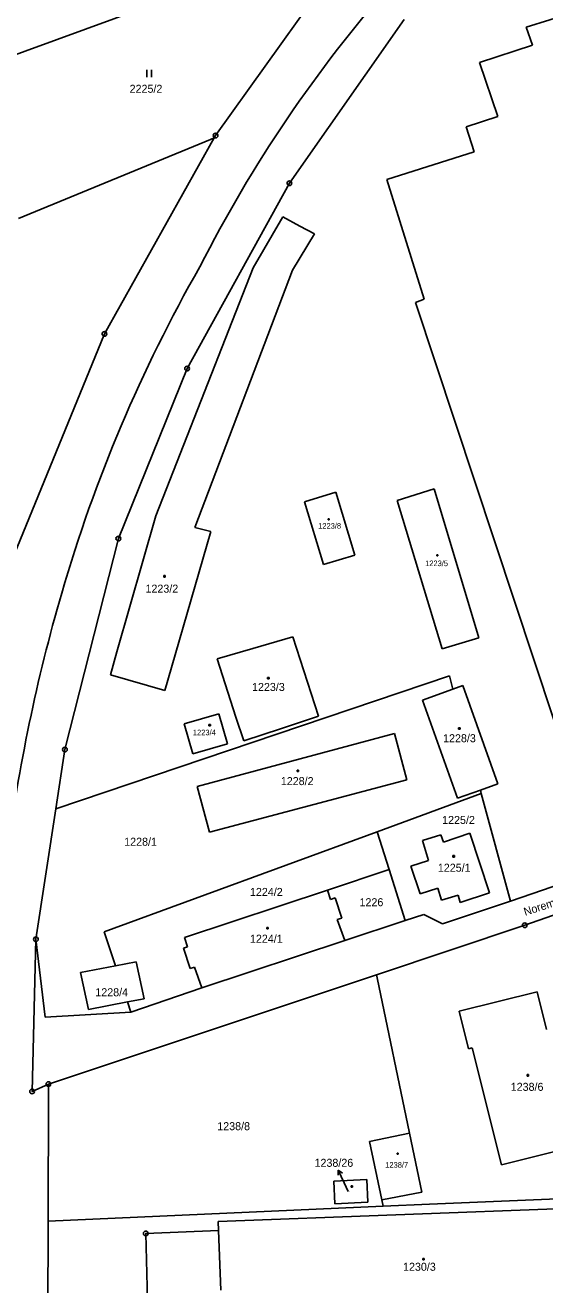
# Model space of a CAD drawing. Extents: x -468021 to -466942, y -1130484 to -1128584.
# Drawn here: x -467804.6 to -467694.3, y -1130340.9 to -1130073.3 of the extents above; entities that cross this region are included whole.
import ezdxf

# ---------------------------------------------------------------- set-up
doc = ezdxf.new("R2010")
doc.units = 0
doc.layers.add('DKM', color=7, linetype='Continuous')

msp = doc.modelspace()

# ---------------------------------------------------------------- linework, layer by layer
at = {"layer": 'DKM'}
for p, q in [((-467741.81, -1130055.85), (-467816.55, -1130083.23)), ((-467764.16, -1130096.76), (-467739.1, -1130061.73)), ((-467698.19, -1130073.72), (-467683.29, -1130069.06)), ((-467724.09, -1130072.13), (-467748.48, -1130106.91)), ((-467696.84, -1130077.55), (-467698.19, -1130073.72)), ((-467708.11, -1130081.28), (-467696.84, -1130077.55)), ((-467778.75, -1130084.33), (-467778.75, -1130082.83)), ((-467777.75, -1130082.83), (-467777.75, -1130084.33)), ((-467704.26, -1130092.75), (-467708.11, -1130081.28)), ((-467710.96, -1130094.89), (-467704.26, -1130092.75)), ((-467764.45, -1130097.28), (-467764.16, -1130096.76)), ((-467709.26, -1130100.25), (-467710.96, -1130094.89)), ((-467806, -1130114.37), (-467765.23, -1130097.6)), ((-467787.76, -1130138.9), (-467764.45, -1130097.28)), ((-467764.45, -1130097.28), (-467765.23, -1130097.6)), ((-467727.8, -1130106.08), (-467709.26, -1130100.25)), ((-467748.48, -1130106.91), (-467770.2, -1130146.26)), ((-467719.86, -1130131.5), (-467727.8, -1130106.08)), ((-467756.15, -1130124.88), (-467749.86, -1130114.04)), ((-467749.86, -1130114.04), (-467746.27, -1130116.02)), ((-467743.17, -1130117.61), (-467747.84, -1130125.37)), ((-467746.27, -1130116.02), (-467743.17, -1130117.61)), ((-467776.8, -1130177.53), (-467756.15, -1130124.88)), ((-467747.84, -1130125.37), (-467768.53, -1130179.99)), ((-467721.72, -1130132.2), (-467719.86, -1130131.5)), ((-467683.82, -1130246.69), (-467721.72, -1130132.2)), ((-467787.76, -1130138.9), (-467808.91, -1130190.65)), ((-467770.2, -1130146.26), (-467784.79, -1130182.37)), ((-467725.63, -1130174.28), (-467717.76, -1130171.78)), ((-467717.76, -1130171.78), (-467708.26, -1130203.48)), ((-467745.3, -1130174.55), (-467738.59, -1130172.53)), ((-467741.27, -1130187.91), (-467745.3, -1130174.55)), ((-467738.59, -1130172.53), (-467734.57, -1130185.9)), ((-467716.05, -1130205.82), (-467725.63, -1130174.28)), ((-467785.09, -1130206.42), (-467776.8, -1130177.53)), ((-467740.23, -1130178.18), (-467740.02, -1130178.18)), ((-467740.23, -1130178.39), (-467740.23, -1130178.18)), ((-467740.02, -1130178.39), (-467740.23, -1130178.39)), ((-467740.02, -1130178.18), (-467740.02, -1130178.39)), ((-467784.79, -1130182.37), (-467796.14, -1130227.19)), ((-467765.16, -1130180.85), (-467773.49, -1130209.76)), ((-467768.53, -1130179.99), (-467765.16, -1130180.85)), ((-467734.57, -1130185.9), (-467741.27, -1130187.91)), ((-467717.15, -1130185.85), (-467716.94, -1130185.85)), ((-467717.15, -1130186.06), (-467717.15, -1130185.85)), ((-467716.94, -1130186.06), (-467717.15, -1130186.06)), ((-467716.94, -1130185.85), (-467716.94, -1130186.06)), ((-467775.16, -1130190.25), (-467774.86, -1130190.25)), ((-467775.16, -1130190.55), (-467775.16, -1130190.25)), ((-467774.86, -1130190.55), (-467775.16, -1130190.55)), ((-467774.86, -1130190.25), (-467774.86, -1130190.55)), ((-467756.23, -1130205.72), (-467747.74, -1130203.26)), ((-467747.74, -1130203.26), (-467742.27, -1130220.08)), ((-467708.26, -1130203.48), (-467716.05, -1130205.82)), ((-467785.09, -1130206.42), (-467786.49, -1130211.3)), ((-467763.83, -1130207.89), (-467756.23, -1130205.72)), ((-467759.83, -1130220.34), (-467763.83, -1130207.89)), ((-467798.06, -1130239.81), (-467714.5, -1130211.55)), ((-467774.9, -1130214.64), (-467786.49, -1130211.3)), ((-467773.49, -1130209.76), (-467774.9, -1130214.64)), ((-467753.09, -1130211.87), (-467752.79, -1130211.87)), ((-467753.09, -1130212.17), (-467753.09, -1130211.87)), ((-467752.79, -1130211.87), (-467752.79, -1130212.17)), ((-467714.5, -1130211.55), (-467713.75, -1130214.33)), ((-467752.79, -1130212.17), (-467753.09, -1130212.17)), ((-467720.25, -1130216.68), (-467713.75, -1130214.33)), ((-467713.75, -1130214.33), (-467711.66, -1130213.57)), ((-467711.66, -1130213.57), (-467704.22, -1130234.46)), ((-467712.81, -1130237.52), (-467720.25, -1130216.68)), ((-467770.85, -1130221.75), (-467763.45, -1130219.59)), ((-467763.45, -1130219.59), (-467761.62, -1130226)), ((-467768.99, -1130228.09), (-467770.85, -1130221.75)), ((-467765.56, -1130221.85), (-467765.26, -1130221.85)), ((-467765.56, -1130222.15), (-467765.56, -1130221.85)), ((-467765.26, -1130222.15), (-467765.56, -1130222.15)), ((-467765.26, -1130221.85), (-467765.26, -1130222.15)), ((-467758.14, -1130225.34), (-467759.83, -1130220.34)), ((-467750.17, -1130222.72), (-467758.14, -1130225.34)), ((-467742.27, -1130220.08), (-467750.17, -1130222.72)), ((-467712.55, -1130222.55), (-467712.25, -1130222.55)), ((-467712.55, -1130222.85), (-467712.55, -1130222.55)), ((-467712.25, -1130222.55), (-467712.25, -1130222.85)), ((-467701.52, -1130259.42), (-467590.03, -1130220.55)), ((-467726.17, -1130223.75), (-467768.08, -1130235.04)), ((-467723.54, -1130233.63), (-467726.17, -1130223.75)), ((-467712.25, -1130222.85), (-467712.55, -1130222.85)), ((-467796.14, -1130227.19), (-467798.06, -1130239.81)), ((-467761.62, -1130226), (-467768.99, -1130228.09)), ((-467588.75, -1130226.09), (-467698.52, -1130264.5)), ((-467746.84, -1130231.54), (-467746.54, -1130231.54)), ((-467746.84, -1130231.84), (-467746.84, -1130231.54)), ((-467746.54, -1130231.84), (-467746.84, -1130231.84)), ((-467746.54, -1130231.54), (-467746.54, -1130231.84)), ((-467768.08, -1130235.04), (-467765.44, -1130244.75)), ((-467765.44, -1130244.75), (-467723.54, -1130233.63)), ((-467707.93, -1130235.78), (-467712.81, -1130237.52)), ((-467704.22, -1130234.46), (-467707.93, -1130235.78)), ((-467707.93, -1130235.78), (-467707.73, -1130236.52)), ((-467707.73, -1130236.52), (-467729.87, -1130244.66)), ((-467707.73, -1130236.52), (-467701.52, -1130259.42)), ((-467798.06, -1130239.81), (-467802.28, -1130267.49)), ((-467729.87, -1130244.66), (-467787.77, -1130265.94)), ((-467729.87, -1130244.66), (-467727.33, -1130252.68)), ((-467720.25, -1130246.52), (-467716.32, -1130245.28)), ((-467720.25, -1130246.52), (-467718.93, -1130250.77)), ((-467715.78, -1130246.89), (-467716.32, -1130245.28)), ((-467710.14, -1130244.96), (-467715.78, -1130246.89)), ((-467706.01, -1130257.63), (-467710.14, -1130244.96)), ((-467718.93, -1130250.77), (-467722.69, -1130251.94)), ((-467722.69, -1130251.94), (-467720.73, -1130257.86)), ((-467713.75, -1130249.72), (-467713.45, -1130249.72)), ((-467713.75, -1130250.02), (-467713.75, -1130249.72)), ((-467713.45, -1130250.02), (-467713.75, -1130250.02)), ((-467713.45, -1130249.72), (-467713.45, -1130250.02)), ((-467727.33, -1130252.68), (-467740.41, -1130257.03)), ((-467727.33, -1130252.68), (-467723.9, -1130263.53)), ((-467770.74, -1130267.12), (-467740.41, -1130257.03)), ((-467740.41, -1130257.03), (-467739.75, -1130259.01)), ((-467720.73, -1130257.86), (-467716.95, -1130256.63)), ((-467716.95, -1130256.63), (-467716.15, -1130259.18)), ((-467738.79, -1130258.7), (-467739.75, -1130259.01)), ((-467737.37, -1130262.98), (-467738.79, -1130258.7)), ((-467716.15, -1130259.18), (-467712.66, -1130258.1)), ((-467715.99, -1130264.18), (-467701.52, -1130259.42)), ((-467712.66, -1130258.1), (-467712.23, -1130259.68)), ((-467712.23, -1130259.68), (-467706.01, -1130257.63)), ((-467723.9, -1130263.53), (-467719.93, -1130262.22)), ((-467719.93, -1130262.22), (-467715.99, -1130264.18)), ((-467753.29, -1130264.97), (-467752.99, -1130264.97)), ((-467753.29, -1130265.27), (-467753.29, -1130264.97)), ((-467752.99, -1130265.27), (-467753.29, -1130265.27)), ((-467752.99, -1130264.97), (-467752.99, -1130265.27)), ((-467738.32, -1130263.3), (-467737.37, -1130262.98)), ((-467736.73, -1130267.77), (-467738.32, -1130263.3)), ((-467736.73, -1130267.77), (-467723.9, -1130263.53)), ((-467698.52, -1130264.5), (-467730, -1130275.01)), ((-467802.28, -1130267.49), (-467803.11, -1130299.81)), ((-467802.28, -1130267.49), (-467800.35, -1130284.06)), ((-467787.77, -1130265.94), (-467785.41, -1130273.12)), ((-467770.74, -1130267.12), (-467770.08, -1130269.11)), ((-467767.05, -1130277.77), (-467736.73, -1130267.77)), ((-467770.08, -1130269.11), (-467770.97, -1130269.4)), ((-467770.97, -1130269.4), (-467769.54, -1130273.69)), ((-467785.41, -1130273.12), (-467792.84, -1130274.54)), ((-467781, -1130272.27), (-467785.41, -1130273.12)), ((-467779.33, -1130280.12), (-467781, -1130272.27)), ((-467769.54, -1130273.69), (-467768.65, -1130273.4)), ((-467768.65, -1130273.4), (-467767.05, -1130277.77)), ((-467730, -1130275.01), (-467799.64, -1130298.24)), ((-467792.84, -1130274.54), (-467791.16, -1130282.43)), ((-467729.87, -1130275.65), (-467730, -1130275.01)), ((-467722.99, -1130308.66), (-467729.87, -1130275.65)), ((-467767.05, -1130277.77), (-467782.17, -1130282.95)), ((-467712.46, -1130282.75), (-467695.86, -1130278.62)), ((-467695.86, -1130278.62), (-467693.87, -1130286.64)), ((-467791.16, -1130282.43), (-467782.87, -1130280.81)), ((-467782.87, -1130280.81), (-467779.33, -1130280.12)), ((-467782.87, -1130280.81), (-467782.17, -1130282.95)), ((-467800.35, -1130284.06), (-467782.17, -1130282.95)), ((-467712.46, -1130282.75), (-467710.47, -1130290.76)), ((-467709.65, -1130290.56), (-467710.47, -1130290.76)), ((-467703.48, -1130315.4), (-467709.65, -1130290.56)), ((-467698, -1130296.23), (-467697.7, -1130296.23)), ((-467698, -1130296.53), (-467698, -1130296.23)), ((-467697.7, -1130296.53), (-467698, -1130296.53)), ((-467697.7, -1130296.23), (-467697.7, -1130296.53)), ((-467799.64, -1130298.24), (-467803.11, -1130299.81)), ((-467799.72, -1130327.35), (-467799.64, -1130299.83)), ((-467799.64, -1130299.83), (-467799.64, -1130298.24)), ((-467731.45, -1130310.41), (-467722.99, -1130308.66)), ((-467728.88, -1130322.85), (-467731.45, -1130310.41)), ((-467722.99, -1130308.66), (-467720.34, -1130321.24)), ((-467725.59, -1130312.91), (-467725.38, -1130312.91)), ((-467725.59, -1130313.12), (-467725.59, -1130312.91)), ((-467725.38, -1130313.12), (-467725.59, -1130313.12)), ((-467725.38, -1130312.91), (-467725.38, -1130313.12)), ((-467686.04, -1130311.07), (-467703.48, -1130315.4)), ((-467739.03, -1130318.9), (-467732.07, -1130318.54)), ((-467738.82, -1130323.71), (-467739.03, -1130318.9)), ((-467738.09, -1130316.5), (-467738.13, -1130317.62)), ((-467736.85, -1130319.23), (-467738.09, -1130316.5)), ((-467738.09, -1130316.5), (-467737.22, -1130317.2)), ((-467732.07, -1130318.54), (-467731.8, -1130323.34)), ((-467736, -1130321.09), (-467736.85, -1130319.23)), ((-467735.37, -1130319.85), (-467735.07, -1130319.85)), ((-467735.37, -1130320.15), (-467735.37, -1130319.85)), ((-467735.07, -1130320.15), (-467735.37, -1130320.15)), ((-467735.07, -1130319.85), (-467735.07, -1130320.15)), ((-467720.34, -1130321.24), (-467728.88, -1130322.85)), ((-467799.72, -1130327.35), (-467728.59, -1130324.15)), ((-467731.8, -1130323.34), (-467738.82, -1130323.71)), ((-467728.59, -1130324.15), (-467728.88, -1130322.85)), ((-467728.59, -1130324.15), (-467718.71, -1130323.75)), ((-467718.71, -1130323.75), (-467674.35, -1130321.92)), ((-467763.62, -1130327.45), (-467686.97, -1130324.53)), ((-467799.81, -1130358.16), (-467799.72, -1130327.35)), ((-467763.55, -1130329.32), (-467778.96, -1130329.97)), ((-467763.55, -1130329.32), (-467763.62, -1130327.45)), ((-467763.05, -1130342), (-467763.55, -1130329.32)), ((-467778.96, -1130329.97), (-467778.22, -1130357.43)), ((-467720.13, -1130335.3), (-467719.83, -1130335.3)), ((-467720.13, -1130335.6), (-467720.13, -1130335.3)), ((-467719.83, -1130335.6), (-467720.13, -1130335.6)), ((-467719.83, -1130335.3), (-467719.83, -1130335.6))]:
    msp.add_line(p, q, dxfattribs=at)
for centre, radius in [((-467764.16, -1130096.76), 0.5), ((-467764.16, -1130096.76), 0.01), ((-467748.48, -1130106.91), 0.5), ((-467748.48, -1130106.91), 0.01), ((-467787.76, -1130138.9), 0.5), ((-467787.76, -1130138.9), 0.01), ((-467770.2, -1130146.26), 0.5), ((-467770.2, -1130146.26), 0.01), ((-467784.79, -1130182.37), 0.5), ((-467784.79, -1130182.37), 0.01), ((-467796.14, -1130227.19), 0.5), ((-467796.14, -1130227.19), 0.01), ((-467698.52, -1130264.5), 0.5), ((-467698.52, -1130264.5), 0.01), ((-467802.28, -1130267.49), 0.5), ((-467802.28, -1130267.49), 0.01), ((-467803.11, -1130299.81), 0.5), ((-467803.11, -1130299.81), 0.01), ((-467799.64, -1130298.24), 0.5), ((-467799.64, -1130298.24), 0.01), ((-467778.96, -1130329.97), 0.5), ((-467778.96, -1130329.97), 0.01)]:
    msp.add_circle(centre, radius, dxfattribs=at)
for centre, radius, start, end in [((-467510.65, -1130254.73), 287.9, 138.6103, 153.141), ((-467490.82, -1130282.57), 318.56, 150.2846, 163.8501), ((-467446.54, -1130295.78), 364.77, 163.7908, 172.7579)]:
    msp.add_arc(centre, radius, start, end, dxfattribs=at)

# ---------------------------------------------------------------- texts
for s, height, p in [('2225/2', 1.7, (-467782.4, -1130087.68)), ('1223/8', 1.19, (-467742.37, -1130180.28)), ('1223/5', 1.19, (-467719.66, -1130188.23)), ('1223/2', 1.7, (-467779.03, -1130193.86)), ('1223/3', 1.7, (-467756.41, -1130214.74)), ('1223/4', 1.19, (-467768.97, -1130224.16)), ('1228/3', 1.7, (-467715.85, -1130225.63)), ('1228/2', 1.7, (-467750.3, -1130234.74)), ('1225/2', 1.7, (-467716.05, -1130242.99)), ('1228/1', 1.7, (-467783.55, -1130247.62)), ('1225/1', 1.7, (-467716.96, -1130253.14)), ('1224/2', 1.7, (-467756.85, -1130258.28)), ('1226', 1.7, (-467733.59, -1130260.47)), ('1224/1', 1.7, (-467756.85, -1130268.22)), ('1228/4', 1.7, (-467789.68, -1130279.59)), ('1238/6', 1.7, (-467701.49, -1130299.68)), ('1238/8', 1.7, (-467763.79, -1130308.04)), ('1238/26', 1.7, (-467743.14, -1130315.82)), ('1238/7', 1.19, (-467728.13, -1130316.01)), ('1238/26', 0.1, (-467736, -1130321.09)), ('1230/3', 1.7, (-467724.35, -1130337.9))]:
    msp.add_text(s, height=height, dxfattribs=at).set_placement(p)
msp.add_text('Noremská', height=1.7, rotation=17.9391, dxfattribs=at).set_placement((-467698.41, -1130262.52))

doc.saveas('drawing.dxf')
